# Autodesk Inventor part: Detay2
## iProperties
Shininess: 20.0
Created: 2001-04
Part Number: Detay2
Document SubType Name: Modeling
Designer: Administrator
Stock Number: ADSK-103540
Density: 1 g/cm^3
Density: 0.0
Volumn: 0.0
Area: 0.0
PropertySet Name: Model Information
Control State: 0
Master: False
Checked Out: False
Author: Administrator
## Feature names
1. Extrusion1
2. Extrusion2
3. Extrusion3
4. Chamfer1
5. Chamfer2
6. Hole1
7. Hole2
8. Hole3
9. Hole4
10. Hole5
11. Extrusion4
12. Fillet1
13. Extrusion5
14. Extrusion6
15. Rectangular Pattern1
16. Rectangular Pattern2
17. Rectangular Pattern3
